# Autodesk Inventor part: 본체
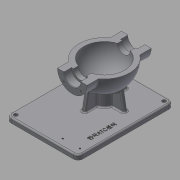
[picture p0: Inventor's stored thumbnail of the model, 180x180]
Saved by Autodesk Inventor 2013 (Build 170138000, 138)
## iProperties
Created: 2015-12
Part Number: 본체
Material: 일반
Document SubType Name: Modeling
Designer: mduedu
Density: 1 g/cm^3
Mass: 512.309 g
Surface Area: 1121.73 cm^2
Volume: 512.309 cm^3
Author: mduedu
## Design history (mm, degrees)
sketch "스케치1"
  geometry: L1 (-53, 0)-(53, 0); A1 r 53 centre (0, 0) between (53, 0) and (-53, 0); 2 further points
  constraints: 2 coincident, 2 end point, 2 point on circle, 1 centre point, 1 horizontal, 1 midpoint
  dimensions: "d0" = 53 radius of A1
revolve "회전1" sketch "스케치1" stored, may be unused: angle "d2" = 90 deg
feature "쉘1" dims "d11" = 10
node "작업 평면1"
sketch "스케치2"
  geometry: C1 r 31 at (0, 0); 1 further point
  constraints: 1 centre point, 1 coincident
  dimensions: "d4" = 62 diameter of C1
extrude "돌출1" join sketch "스케치2" stored distance "d5" = 10; taper "d6" = 0 deg
hole "구멍1" diameter "d14" = 35; stored, may be unused: countersink angle "d18" = 90 deg, drill point angle "d20" = 0 deg; dims "d12" = 10, "d13" = 10, "d15" = 6, "d16" = 4, "d17" = 2, "d19" = 16
hole "구멍2" diameter "d23" = 27; stored, may be unused: countersink angle "d27" = 90 deg, drill point angle "d29" = 0 deg; dims "d21" = 10, "d22" = 10, "d24" = 6, "d25" = 4, "d26" = 2, "d28" = 16
fillet "모깎기1" dims "d30" = 0.3
chamfer "모따기1" distance "d40" = 1; stored, may be unused: second distance "d41" = 2, angle "d42" = 45 deg
sketch "스케치4"
  geometry: L1 (0, 0)-(0, -25); L2 (0, 0)-(-17.678, -17.678); A1 r 25 centre (0, 0) between (-17.678, -17.678) and (0, -25); 1 further point
  constraints: 4 end point, 2 point on circle, 1 centre point, 1 coincident, 1 vertical
  dimensions: "d43" = 50 diameter of A1; "d47" = 45 deg angle of L1 L2
hole "구멍4" sketch "스케치4" at (-17.678, -17.678) diameter "d49" = 3.242; stored, may be unused: countersink angle "d53" = 90 deg, drill point angle "d55" = 118 deg; dims "d50" = 11, "d51" = 4, "d52" = 2, "d54" = 13
node "작업 평면3"
sketch "스케치6" dims "d22" = 10
  geometry: L1 (-70, -75)-(130, -75); L2 (130, -75)-(130, 75); L3 (130, 75)-(-70, 75); L4 (-70, 75)-(-70, -75); 2 further points
  constraints: 8 end point, 2 parallel, 1 coincident, 1 horizontal, 1 perpendicular
  dimensions: "d158" = 200 distance of L3.end L2.end; "d159" = 150 distance of L2.end L1.end; "d162" = 75 distance from line of L1 point (0, 0); "d163" = 70 distance from line of L4 point (0, 0)
extrude "돌출3" join sketch "스케치6" distance "d80" = 10; taper "d81" = 0 deg
sketch "스케치7"
  geometry: C1 r 20 at (0, 0); 2 further points
  constraints: 2 coincident, 1 centre point
  dimensions: "d82" = 40 diameter of C1
extrude "돌출4" join sketch "스케치7" stored distance "d84" = 10; taper "d85" = 0 deg
sketch "스케치8"
  geometry: 3 further points
  constraints: 2 coincident
hole "구멍6" sketch "스케치8" at (0, 0) diameter "d86" = 20; stored, may be unused: countersink angle "d90" = 90 deg, drill point angle "d92" = 118 deg; dims "d87" = 7, "d88" = 40, "d89" = 5, "d91" = 10
fillet "모깎기2" dims "d93" = 0.3
sketch "스케치9"
  geometry: L1 (-45, -75)-(-38.245, -36.692); L2 (70, -75)-(-130, -75) reference; A1 r 53 centre (0, 0) between (42.988, 31) and (42.988, -31) reference; 1 further point
  constraints: 2 end point, 1 coincident, 1 point on circle, 1 point on line
  dimensions: "d94" = 45 horizontal distance of L1.start point (0, 0); "d160" = 80 deg angle of L2 L1
feature "리브1" sketch "스케치9" dims "d96" = 1, "d97" = 8, "d98" = 0, "d99" = 0, "d100" = 1, "d101" = 1
fillet "모깎기3" dims "d120" = 3
fillet "모깎기4" dims "d121" = 3, "d122" = 3
fillet "모깎기5" dims "d123" = 3
sketch "스케치12"
  geometry: L1 (0, 100)-(0, -100); L2 (0, 100)-(100, 100); L3 (100, 100)-(100, -100); L4 (100, -100)-(0, -100); 2 further points
  constraints: 8 end point, 3 perpendicular, 1 coincident, 1 midpoint, 1 vertical
  dimensions: "d127" = 200 distance of L2.end L3.end; "d129" = 100 distance between parallel lines of L1 L3
extrude "돌출5" cut sketch "스케치12" stored distance "d130" = 10; taper "d131" = 0 deg
fillet "모깎기10" dims "d164" = 10
fillet "모깎기11" dims "d165" = 3
sketch "스케치15"
  geometry: C1 r 4 at (-120, 65); C2 r 4 at (60, 65); C3 r 4 at (60, -65); A1 r 10 centre (-120, 65) between (-120, 75) and (-130, 65) reference; A2 r 10 centre (60, 65) between (70, 65) and (60, 75) reference; A3 r 10 centre (60, -65) between (60, -75) and (70, -65) reference; 1 further point
  constraints: 3 centre point, 3 coincident, 2 equal radius
  dimensions: "d166" = 8 diameter of C1
extrude "돌출8" cut sketch "스케치15" stored distance "d167" = 10; taper "d168" = 0 deg
sketch "스케치16"
  geometry: L1 (-130, 65)-(-130, -65) reference; L2 (-120, -75)-(60, -75) reference; 2 further points
  constraints: 1 other
  dimensions: "d169" = 70 distance from line of point (-60, -55) L1; "d170" = 20 distance from line of point (-60, -55) L2
feature "엠보싱2" sketch "스케치16" dims "d171" = 0.5, "d172" = 0
sketch "스케치17"
  geometry: L1 (-120, 75)-(60, 75) reference; L2 (-130, -65)-(-130, 65) reference; 2 further points
  constraints: 1 vertical alignment
  dimensions: "d180" = 12 distance from line of L1 point (-114, 63); "d181" = 16 distance from line of point (-114, 63) L2; "d182" = 36 distance of point (-114, 27) point (-114, 63)
hole "구멍9" sketch "스케치17" at (-114, 63), (-114, 27) diameter "d173" = 3.242; stored, may be unused: countersink angle "d177" = 90 deg, drill point angle "d179" = 0 deg; dims "d174" = 6, "d175" = 4, "d176" = 2, "d178" = 8
node "솔리드1"
mirror "대칭1"
mirror "대칭2"
pattern_circular "원형 패턴1" dims angle "d57" = 360 deg
mirror "대칭3"
pattern_circular "원형 패턴3" dims angle "d103" = 360 deg
other parameters: "d3" = 67, "d77" = -85
